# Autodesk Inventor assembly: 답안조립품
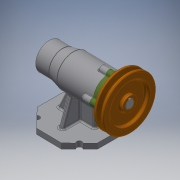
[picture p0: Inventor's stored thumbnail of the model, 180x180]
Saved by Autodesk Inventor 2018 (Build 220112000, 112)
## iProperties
Created: 2019-12
Part Number: 답안조립품
Document SubType Name: Assembly
Designer: Administrator
Author: Administrator
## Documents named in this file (12)
- C:\Users\Administrator\Desktop\491204V1016\답안조립품.iam
- C:\Users\Administrator\Desktop\491204V1016\Ű 5 x 5 x 16.ipt
- C:\Users\Administrator\Desktop\491204V1016\V벨트풀리.ipt
- C:\Users\Administrator\Desktop\491204V1016\멈춤나사 M3.ipt
- C:\Users\Administrator\Desktop\491204V1016\베어링 6004.ipt
- C:\Users\Administrator\Desktop\491204V1016\베어링 51202.ipt
- C:\Users\Administrator\Desktop\491204V1016\본체.ipt
- C:\Users\Administrator\Desktop\491204V1016\볼트 M4.ipt
- C:\Users\Administrator\Desktop\491204V1016\어댑터슬리브.ipt
- C:\Users\Administrator\Desktop\491204V1016\오일 실.ipt
- C:\Users\Administrator\Desktop\491204V1016\축.ipt
- C:\Users\Administrator\Desktop\491204V1016\커버.ipt
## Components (2 placed, 2 different names)
1. Ű 5 x 5 x 16:1 — 각도:1
2. V벨트풀리:1 — 각도:2, 각도:3
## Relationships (3: Angle 3)
- 각도:1 [Angle]: Ű 5 x 5 x 16:1
- 각도:2 [Angle]: V벨트풀리:1
- 각도:3 [Angle]: V벨트풀리:1
